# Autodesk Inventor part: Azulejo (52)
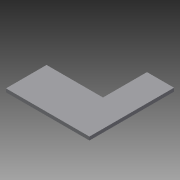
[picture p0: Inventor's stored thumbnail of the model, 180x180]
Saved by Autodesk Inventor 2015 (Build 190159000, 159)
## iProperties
Created: 2015-04
Part Number: Azulejo (52)
Material: Genérico
Document SubType Name: Modeling
Designer: Felipe
Density: 1 g/cm^3
Appearance: Padrão
Author: Felipe
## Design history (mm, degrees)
sketch "Sketch1" dims "d0" = 60
  geometry: L1 (95.589, 796.693)-(95.589, 56.693); L2 (1575.589, 56.693)-(1575.589, 1556.693); L3 (95.589, 56.693)-(1575.589, 56.693); L4 (1095.589, 1556.693)-(1095.589, 776.693); L5 (1095.589, 776.693)-(95.589, 776.693); L6 (95.589, 1556.693)-(1575.589, 1556.693); L7 (1575.589, 1556.693)-(1575.589, 1616.693); L8 (1575.589, 1616.693)-(95.589, 1616.693); L9 (95.589, 1616.693)-(95.589, 1556.693); 1 further point
  constraints: 18 end point, 2 point on line
extrude "Extrusion1" new body sketch "Sketch1" distance "d0" = 60; taper "d1" = 0 deg
body "Solid1"
